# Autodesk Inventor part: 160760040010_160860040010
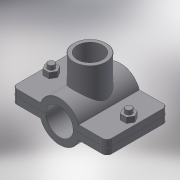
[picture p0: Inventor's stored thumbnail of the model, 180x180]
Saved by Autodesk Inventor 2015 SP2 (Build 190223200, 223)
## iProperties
Created: 2017-05
Part Number: 160760040010_160860040010
Material: Generic
Description: PLASSON SADDLE 40-1"
Document SubType Name: Modeling
Designer: KIM
Density: 1 g/cm^3
Appearance: Default
Author: KIM
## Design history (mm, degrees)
derived "16076.ipt"
feature "Solid1::16076.ipt"
feature "Solid2::16076.ipt"
tag "TaggingFeature1"
body "Solid1"
other parameters: "d0" = 56, "d1" = 92, "d5" = 0, "d6" = 4.6, "d7" = 92, "d8" = 0.1, "d10" = 0, "d11" = 0.4, "d14" = 39.3783, "d20" = 0.4, "d23" = 0.4, "d37" = 8, "d38" = 28, "d39" = 0, "d40" = 3, "d41" = 5, "d42" = 0, "d43" = 6, "d44" = 3, "d45" = 0, "d46" = 0.4, "d51" = 49, "d52" = 30.291, "d53" = 21, "d54" = 0, "d55" = 25, "d57" = 0, "d58" = 43.2, "d60" = 0, "d66" = 0, "B_" = 25, "G_" = 30.291, "A_" = 49, "L_" = 92, "l_2" = 21
